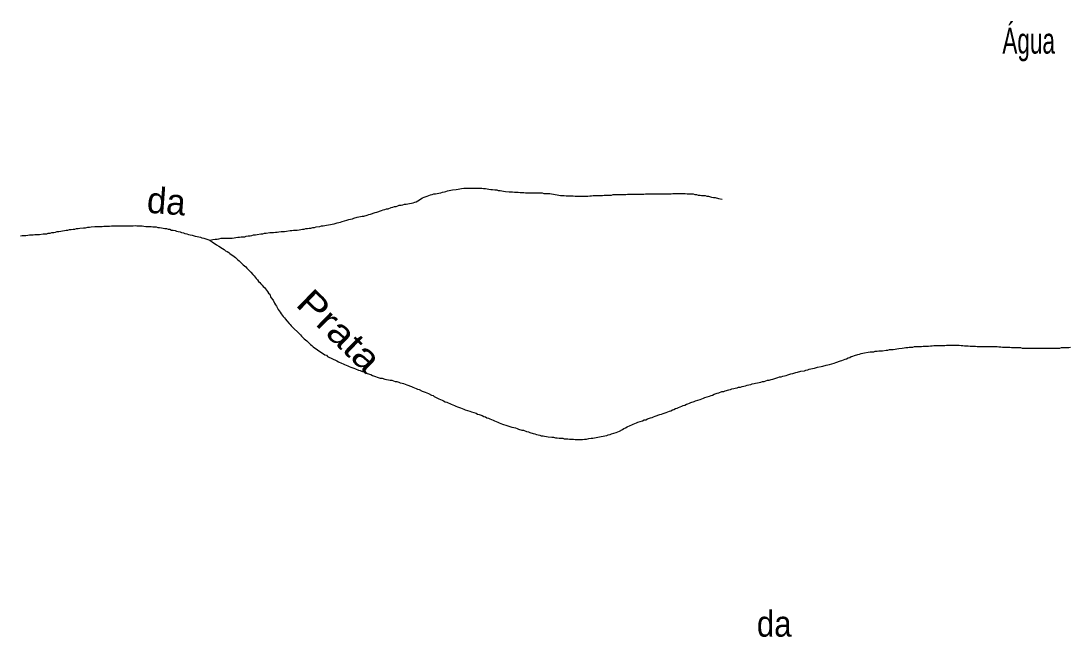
# Model space of a CAD drawing. Extents: x 652.3 to 678, y 7316.9 to 7344.9.
# Drawn here: x 666.71 to 669.946, y 7330.926 to 7332.828 of the extents above; entities that cross this region are included whole.
import ezdxf
from ezdxf.enums import TextEntityAlignment as Align

# ---------------------------------------------------------------- set-up
doc = ezdxf.new("R2010")
doc.units = 0
doc.header["$LTSCALE"] = 0.032
doc.layers.add('61', color=7, linetype='Continuous')
doc.layers.add('7', color=7, linetype='Continuous', lineweight=25)

msp = doc.modelspace()

# ---------------------------------------------------------------- linework, layer by layer
at = {"layer": '7'}
for points in [[(667.9099, 7332.2642), (667.9155, 7332.265), (667.9211, 7332.2666), (667.9258, 7332.2682), (667.9306, 7332.2698), (667.9354, 7332.2722), (667.9402, 7332.2754), (667.9449, 7332.2786), (667.9497, 7332.2817), (667.9545, 7332.2841), (667.964, 7332.2873), (667.9696, 7332.2889), (667.9744, 7332.2913), (667.9799, 7332.2921), (667.9847, 7332.2937), (667.9903, 7332.2937), (667.9951, 7332.2953), (668.0006, 7332.2961), (668.0062, 7332.2977), (668.0118, 7332.2992), (668.0173, 7332.3), (668.0221, 7332.3016), (668.0269, 7332.3032), (668.0325, 7332.304), (668.0372, 7332.3056), (668.0428, 7332.3064), (668.0539, 7332.308), (668.0595, 7332.3088), (668.0707, 7332.3104), (668.077, 7332.3112), (668.1327, 7332.3112), (668.1383, 7332.3104), (668.1439, 7332.3104), (668.155, 7332.3088), (668.1606, 7332.308), (668.1661, 7332.3072), (668.1733, 7332.3064), (668.1789, 7332.3064), (668.1836, 7332.3048), (668.1892, 7332.304), (668.2003, 7332.3024), (668.2059, 7332.3016), (668.2171, 7332.3), (668.2282, 7332.3), (668.2338, 7332.2992), (668.2449, 7332.2992), (668.2513, 7332.2985), (668.2624, 7332.2985), (668.268, 7332.2977), (668.2743, 7332.2969), (668.3022, 7332.2969), (668.3078, 7332.2977), (668.3133, 7332.2977), (668.3197, 7332.2969), (668.3245, 7332.2953), (668.3428, 7332.2953), (668.3483, 7332.2937), (668.3539, 7332.2929), (668.3595, 7332.2921), (668.3651, 7332.2913), (668.3706, 7332.2897), (668.3762, 7332.2889), (668.3873, 7332.2889), (668.3929, 7332.2881), (668.4152, 7332.2881), (668.4216, 7332.2873), (668.4605, 7332.2873), (668.4661, 7332.2881), (668.4717, 7332.2881), (668.4772, 7332.2889), (668.5051, 7332.2889), (668.5107, 7332.2897), (668.5162, 7332.2897), (668.5218, 7332.2905), (668.5329, 7332.2905), (668.5385, 7332.2921), (668.5775, 7332.2921), (668.5831, 7332.2929), (668.6332, 7332.2929), (668.6388, 7332.2937), (668.7175, 7332.2937), (668.7223, 7332.2953), (668.7613, 7332.2953), (668.7669, 7332.2945), (668.7732, 7332.2945), (668.7796, 7332.2937), (668.7852, 7332.2937), (668.7907, 7332.2921), (668.7963, 7332.2921), (668.8011, 7332.2905), (668.8067, 7332.2905), (668.8114, 7332.2889), (668.8226, 7332.2889), (668.8274, 7332.2873), (668.8329, 7332.2873), (668.8425, 7332.2841), (668.848, 7332.2833), (668.8536, 7332.2825), (668.864, 7332.2802), (668.8748, 7332.2776), (668.8756, 7332.2775)], [(667.2933, 7332.1513), (667.3028, 7332.1536), (667.31, 7332.1544), (667.3155, 7332.1544), (667.3211, 7332.1552), (667.3283, 7332.1568), (667.3354, 7332.1568), (667.345, 7332.1568), (667.3561, 7332.1568), (667.3617, 7332.1576), (667.3681, 7332.1584), (667.3736, 7332.1592), (667.3792, 7332.16), (667.3848, 7332.16), (667.3895, 7332.1616), (667.4007, 7332.1616), (667.4055, 7332.1632), (667.411, 7332.164), (667.4174, 7332.1648), (667.423, 7332.1656), (667.4277, 7332.1672), (667.4341, 7332.168), (667.4397, 7332.1688), (667.4508, 7332.1703), (667.4572, 7332.1711), (667.462, 7332.1727), (667.4675, 7332.1727), (667.4787, 7332.1743), (667.4842, 7332.1743), (667.4898, 7332.1751), (667.4954, 7332.1759), (667.5009, 7332.1759), (667.5065, 7332.1767), (667.5129, 7332.1775), (667.5184, 7332.1775), (667.524, 7332.1783), (667.5296, 7332.1791), (667.5407, 7332.1807), (667.5463, 7332.1807), (667.5519, 7332.1815), (667.5574, 7332.1823), (667.563, 7332.1823), (667.5686, 7332.1831), (667.5741, 7332.1839), (667.5789, 7332.1855), (667.5845, 7332.1855), (667.5893, 7332.1871), (667.5948, 7332.1871), (667.5996, 7332.1886), (667.6052, 7332.1886), (667.6107, 7332.1902), (667.6163, 7332.1902), (667.6219, 7332.1918), (667.633, 7332.1934), (667.6378, 7332.195), (667.6434, 7332.195), (667.6481, 7332.1966), (667.6537, 7332.1974), (667.6593, 7332.1982), (667.6656, 7332.1998), (667.6712, 7332.2006), (667.6768, 7332.2014), (667.6863, 7332.2046), (667.6919, 7332.2054), (667.6967, 7332.2069), (667.7015, 7332.2085), (667.7158, 7332.2133), (667.7221, 7332.2149), (667.7277, 7332.2157), (667.7333, 7332.2173), (667.7381, 7332.2189), (667.7476, 7332.2221), (667.7532, 7332.2229), (667.7587, 7332.2237), (667.7635, 7332.2252), (667.7691, 7332.2252), (667.7786, 7332.2284), (667.7842, 7332.23), (667.789, 7332.2316), (667.8033, 7332.2364), (667.8089, 7332.238), (667.8232, 7332.2428), (667.828, 7332.2443), (667.8335, 7332.2459), (667.8383, 7332.2475), (667.8439, 7332.2483), (667.8534, 7332.2515), (667.8582, 7332.2531), (667.863, 7332.2547), (667.8685, 7332.2555), (667.8733, 7332.2571), (667.8781, 7332.2587), (667.8837, 7332.2595), (667.8892, 7332.2603), (667.894, 7332.2619), (667.8996, 7332.2619), (667.9044, 7332.2634), (667.9099, 7332.2642)], [(666.7084, 7332.1648), (666.714, 7332.1656), (666.7251, 7332.1656), (666.7307, 7332.1664), (666.7363, 7332.1672), (666.7419, 7332.1672), (666.7474, 7332.168), (666.753, 7332.1688), (666.7673, 7332.1688), (666.7785, 7332.1703), (666.784, 7332.1711), (666.7896, 7332.1711), (666.7944, 7332.1727), (666.7999, 7332.1727), (666.8055, 7332.1743), (666.8111, 7332.1751), (666.8166, 7332.1759), (666.8214, 7332.1775), (666.827, 7332.1775), (666.8326, 7332.1791), (666.8381, 7332.1799), (666.8445, 7332.1807), (666.8493, 7332.1823), (666.8548, 7332.1823), (666.8596, 7332.1839), (666.8652, 7332.1839), (666.8708, 7332.1855), (666.8763, 7332.1855), (666.8811, 7332.1871), (666.8867, 7332.1871), (666.8922, 7332.1879), (666.9034, 7332.1894), (666.9097, 7332.1894), (666.9161, 7332.191), (666.9217, 7332.191), (666.9272, 7332.1918), (666.9384, 7332.1934), (666.9607, 7332.1934), (666.9662, 7332.1942), (666.9829, 7332.1942), (666.9893, 7332.195), (667.0283, 7332.195), (667.0339, 7332.1958), (667.0561, 7332.1958), (667.0625, 7332.1966), (667.0673, 7332.195), (667.084, 7332.195), (667.0896, 7332.1942), (667.0951, 7332.1934), (667.1118, 7332.1934), (667.1166, 7332.1918), (667.1278, 7332.1918), (667.1325, 7332.1902), (667.1381, 7332.1902), (667.1437, 7332.1894), (667.1492, 7332.1886), (667.154, 7332.1871), (667.1596, 7332.1871), (667.1644, 7332.1855), (667.1699, 7332.1847), (667.1747, 7332.1823), (667.1803, 7332.1815), (667.1858, 7332.1807), (667.1906, 7332.1791), (667.1954, 7332.1775), (667.201, 7332.1767), (667.2057, 7332.1751), (667.2113, 7332.1735), (667.2161, 7332.1719), (667.2217, 7332.1703), (667.2272, 7332.1688), (667.2328, 7332.1672), (667.2384, 7332.1664), (667.2479, 7332.1632), (667.2535, 7332.1624), (667.259, 7332.1616), (667.2638, 7332.16), (667.2686, 7332.1584), (667.2742, 7332.1568), (667.2933, 7332.1513)], [(667.2933, 7332.1513), (667.3044, 7332.1425), (667.3092, 7332.1401), (667.314, 7332.1369), (667.3211, 7332.1322), (667.3323, 7332.125), (667.337, 7332.1218), (667.3418, 7332.1186), (667.3466, 7332.1162), (667.3513, 7332.1131), (667.3553, 7332.1099), (667.3593, 7332.1067), (667.3641, 7332.1035), (667.3681, 7332.1003), (667.372, 7332.0971), (667.376, 7332.0932), (667.38, 7332.09), (667.384, 7332.0868), (667.3959, 7332.0749), (667.3999, 7332.0717), (667.4039, 7332.0685), (667.4078, 7332.0645), (667.4198, 7332.0526), (667.4261, 7332.0446), (667.4301, 7332.0406), (667.4333, 7332.0367), (667.4365, 7332.0327), (667.4405, 7332.0287), (667.4436, 7332.0239), (667.4476, 7332.02), (667.4508, 7332.016), (667.4548, 7332.012), (667.458, 7332.008), (667.462, 7332.0048), (667.4651, 7332.0009), (667.4683, 7331.9969), (667.4707, 7331.9921), (667.4739, 7331.9873), (667.4779, 7331.9842), (667.4818, 7331.9738), (667.4882, 7331.9659), (667.493, 7331.9563), (667.4962, 7331.9515), (667.4993, 7331.9468), (667.5041, 7331.9372), (667.5073, 7331.9324), (667.5105, 7331.9285), (667.5137, 7331.9237), (667.52, 7331.9157), (667.5232, 7331.911), (667.5272, 7331.907), (667.5304, 7331.9022), (667.5383, 7331.8942), (667.5415, 7331.8903), (667.5447, 7331.8863), (667.5726, 7331.8584), (667.5765, 7331.8545), (667.5845, 7331.8465), (667.5885, 7331.8433), (667.5924, 7331.8401), (667.6004, 7331.8322), (667.6044, 7331.829), (667.6084, 7331.8258), (667.6123, 7331.8218), (667.6163, 7331.8187), (667.6211, 7331.8155), (667.6251, 7331.8123), (667.6298, 7331.8099), (667.6346, 7331.8067), (667.6394, 7331.8035), (667.6442, 7331.8004), (667.6481, 7331.7972), (667.6529, 7331.7956), (667.6569, 7331.7924), (667.6855, 7331.7781), (667.6903, 7331.7757), (667.6999, 7331.7709), (667.7046, 7331.7693), (667.7094, 7331.7669), (667.7142, 7331.7653), (667.719, 7331.763), (667.7237, 7331.7614), (667.7285, 7331.759), (667.7381, 7331.7558), (667.7428, 7331.7534), (667.7524, 7331.7502), (667.7572, 7331.7486), (667.7619, 7331.7462), (667.7715, 7331.7431), (667.7762, 7331.7407), (667.7858, 7331.7375), (667.7906, 7331.7359), (667.7953, 7331.7335), (667.8049, 7331.7303), (667.8097, 7331.7279), (667.8192, 7331.7248), (667.8256, 7331.7248), (667.8335, 7331.7216), (667.8391, 7331.7208), (667.8447, 7331.72)], [(669.0573, 7331.7295), (669.0621, 7331.7311), (669.0676, 7331.7319), (669.0732, 7331.7335), (669.078, 7331.7351), (669.0875, 7331.7383), (669.0931, 7331.7391), (669.1027, 7331.7423), (669.1082, 7331.7431), (669.1178, 7331.7462), (669.1289, 7331.7478), (669.1337, 7331.7502), (669.1393, 7331.751), (669.144, 7331.7526), (669.1488, 7331.7542), (669.1544, 7331.755), (669.1599, 7331.7558), (669.1695, 7331.759), (669.1806, 7331.7606), (669.1862, 7331.7622), (669.1958, 7331.7653), (669.2069, 7331.7669), (669.2212, 7331.7717), (669.226, 7331.7733), (669.2403, 7331.7781), (669.2451, 7331.7797), (669.2499, 7331.7813), (669.2546, 7331.7836), (669.2594, 7331.7852), (669.2642, 7331.7876), (669.269, 7331.7892), (669.2737, 7331.7916), (669.2785, 7331.7932), (669.2833, 7331.7948), (669.2944, 7331.798), (669.2992, 7331.7996), (669.3048, 7331.8011), (669.3095, 7331.8027), (669.3151, 7331.8035), (669.3262, 7331.8051), (669.3318, 7331.8059), (669.3374, 7331.8067), (669.343, 7331.8067), (669.3477, 7331.8083), (669.3533, 7331.8083), (669.3589, 7331.8091), (669.3644, 7331.8099), (669.37, 7331.8099), (669.3812, 7331.8115), (669.3867, 7331.8115), (669.3923, 7331.8131), (669.3979, 7331.8131), (669.4034, 7331.8139), (669.409, 7331.8147), (669.4146, 7331.8155), (669.4201, 7331.8163), (669.4313, 7331.8179), (669.4368, 7331.8187), (669.4424, 7331.8194), (669.448, 7331.8194), (669.4528, 7331.821), (669.4639, 7331.821), (669.4687, 7331.8226), (669.491, 7331.8226), (669.4957, 7331.8242), (669.5124, 7331.8242), (669.518, 7331.825), (669.5236, 7331.825), (669.5291, 7331.8258), (669.5626, 7331.8258), (669.5681, 7331.8266), (669.6071, 7331.8266), (669.6127, 7331.8258), (669.6183, 7331.8258), (669.6238, 7331.825), (669.635, 7331.825), (669.6405, 7331.8242), (669.6461, 7331.8242), (669.6517, 7331.8234), (669.6573, 7331.8234), (669.6628, 7331.8226), (669.7241, 7331.8226), (669.7297, 7331.8218), (669.7352, 7331.8218), (669.7408, 7331.821), (669.7575, 7331.821), (669.7631, 7331.8202), (669.7687, 7331.8194), (669.7965, 7331.8194), (669.8013, 7331.8179), (669.9182, 7331.8179), (669.923, 7331.8194), (669.9453, 7331.8194), (669.9509, 7331.821)], [(667.8447, 7331.72), (667.8495, 7331.7184), (667.855, 7331.7184), (667.8606, 7331.7168), (667.8654, 7331.7152), (667.8709, 7331.7144), (667.8765, 7331.7128), (667.8813, 7331.7104), (667.8868, 7331.7096), (667.8916, 7331.7081), (667.8964, 7331.7065), (667.9012, 7331.7041), (667.9155, 7331.6993), (667.9203, 7331.6969), (667.925, 7331.6953), (667.9298, 7331.6929), (667.9346, 7331.6913), (667.9394, 7331.6898), (667.9489, 7331.685), (667.9585, 7331.6818), (667.9632, 7331.6794), (667.968, 7331.6778), (667.9776, 7331.673), (667.9823, 7331.6715), (667.9863, 7331.6683), (667.9959, 7331.6635), (668.0006, 7331.6611), (668.0054, 7331.6587), (668.0102, 7331.6571), (668.015, 7331.6547), (668.0197, 7331.6524), (668.0245, 7331.6508), (668.0293, 7331.6484), (668.0341, 7331.6468), (668.0388, 7331.6444), (668.0436, 7331.6428), (668.0484, 7331.6404), (668.0531, 7331.6388), (668.0579, 7331.6364), (668.0675, 7331.6333), (668.0722, 7331.6317), (668.077, 7331.6293), (668.0818, 7331.6277), (668.0961, 7331.6229), (668.1009, 7331.6213), (668.1152, 7331.6165), (668.12, 7331.6142), (668.1248, 7331.6126), (668.1343, 7331.6094), (668.1391, 7331.607), (668.1439, 7331.6054), (668.1486, 7331.603), (668.1534, 7331.6014), (668.1582, 7331.5998), (668.163, 7331.5975), (668.1677, 7331.5951), (668.1725, 7331.5935), (668.1773, 7331.5911), (668.182, 7331.5895), (668.1868, 7331.5871), (668.1916, 7331.5855), (668.1964, 7331.5831), (668.2107, 7331.5784), (668.2163, 7331.5768), (668.2258, 7331.5736), (668.2314, 7331.5728), (668.237, 7331.5712), (668.2417, 7331.5696), (668.2465, 7331.568), (668.256, 7331.5648), (668.2616, 7331.564), (668.2712, 7331.5608), (668.2767, 7331.5593), (668.2815, 7331.5577), (668.2911, 7331.5545), (668.2966, 7331.5529), (668.3014, 7331.5513), (668.307, 7331.5505), (668.3117, 7331.5489), (668.3165, 7331.5473), (668.3221, 7331.5473), (668.3269, 7331.5457), (668.3324, 7331.5449), (668.338, 7331.5441), (668.3491, 7331.5425), (668.3547, 7331.5425), (668.3603, 7331.541), (668.3659, 7331.541), (668.3714, 7331.5402), (668.377, 7331.5394), (668.3826, 7331.5394), (668.3873, 7331.5378), (668.3985, 7331.5378), (668.404, 7331.537), (668.4104, 7331.537), (668.416, 7331.5362), (668.4216, 7331.5354), (668.4438, 7331.5354), (668.4502, 7331.537), (668.4566, 7331.537), (668.4629, 7331.5386)], [(668.4629, 7331.5386), (668.4701, 7331.5394), (668.4757, 7331.5394), (668.4804, 7331.541), (668.486, 7331.5418), (668.4916, 7331.5425), (668.4963, 7331.5441), (668.5019, 7331.5449), (668.5075, 7331.5457), (668.5131, 7331.5473), (668.5186, 7331.5481), (668.5234, 7331.5505), (668.529, 7331.5513), (668.5337, 7331.5529), (668.5481, 7331.5577), (668.5528, 7331.5593), (668.5576, 7331.5616), (668.5672, 7331.5664), (668.5719, 7331.5696), (668.5767, 7331.572), (668.5815, 7331.5744), (668.591, 7331.5792), (668.5958, 7331.5807), (668.6006, 7331.5831), (668.6054, 7331.5847), (668.6101, 7331.5871), (668.6149, 7331.5887), (668.6292, 7331.5935), (668.634, 7331.5959), (668.6396, 7331.5967), (668.6443, 7331.599), (668.6539, 7331.6022), (668.6587, 7331.6038), (668.6634, 7331.6054), (668.6682, 7331.6078), (668.6825, 7331.6126), (668.6873, 7331.6142), (668.6929, 7331.6158), (668.7024, 7331.6189), (668.7072, 7331.6213), (668.712, 7331.6229), (668.7168, 7331.6245), (668.7215, 7331.6269), (668.7263, 7331.6285), (668.7311, 7331.6309), (668.7358, 7331.6325), (668.7406, 7331.6348), (668.7454, 7331.6364), (668.7502, 7331.6388), (668.7549, 7331.6404), (668.7597, 7331.642), (668.7645, 7331.6444), (668.7693, 7331.646), (668.774, 7331.6476), (668.7788, 7331.65), (668.7884, 7331.6531), (668.7931, 7331.6547), (668.8075, 7331.6595), (668.8122, 7331.6611), (668.817, 7331.6635), (668.8218, 7331.6651), (668.8361, 7331.6699), (668.8409, 7331.6715), (668.8457, 7331.673), (668.8504, 7331.6754), (668.86, 7331.6786), (668.8647, 7331.6802), (668.8743, 7331.6834), (668.8799, 7331.6842), (668.8846, 7331.6858), (668.8958, 7331.689), (668.9006, 7331.6905), (668.9053, 7331.6921), (668.9109, 7331.6929), (668.9157, 7331.6945), (668.9212, 7331.6953), (668.926, 7331.6969), (668.9316, 7331.6977), (668.9364, 7331.6993), (668.9419, 7331.7001), (668.9475, 7331.7017), (668.9523, 7331.7033), (668.9578, 7331.7041), (668.9634, 7331.7057), (668.9682, 7331.7073), (668.9738, 7331.7081), (668.9785, 7331.7096), (668.9841, 7331.7104), (668.9889, 7331.712), (668.9944, 7331.7128), (668.9992, 7331.7144), (669.0048, 7331.7152), (669.0104, 7331.7168), (669.0151, 7331.7184), (669.0207, 7331.7192), (669.0263, 7331.7208), (669.0318, 7331.7224), (669.0374, 7331.724), (669.047, 7331.7271), (669.0517, 7331.7287), (669.0573, 7331.7295)]]:
    msp.add_lwpolyline(points, dxfattribs=at)

# ---------------------------------------------------------------- texts
at = {"layer": '61', "width": 0.65}
msp.add_text('Água', height=0.08, dxfattribs=at).set_placement((669.7403, 7332.727))
at = {"layer": '61'}
msp.add_text('da', height=0.08, rotation=355.728, dxfattribs=at).set_placement((667.1562, 7332.2316), align=Align.CENTER)
at = {"layer": '61', "width": 1.2}
msp.add_text('Prata', height=0.08, rotation=315.829, dxfattribs=at).set_placement((667.6649, 7331.8434), align=Align.CENTER)
at = {"layer": '61', "width": 0.9}
msp.add_text('da', height=0.08, dxfattribs=at).set_placement((669.0358, 7330.9269), align=Align.CENTER)

doc.saveas('drawing.dxf')
